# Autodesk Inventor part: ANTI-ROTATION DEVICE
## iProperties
Created: 2007-01
Part Number: ANTI-ROTATION DEVICE
Document SubType Name: Modeling
Designer: Andy Moles
Material: Aluminum-6061
Density: 2.71 g/cm^3
Mass: 6.76867 g
Surface Area: 23.7311 cm^2
Volume: 2.49766 cm^3
Author: Andy Moles
Title: ANTI ROTATION DEVICE
Keywords: ANTI-ROTATION DEVICE FOR ANGLES
Comments: ANTI ROTATION DEVICE FOR ANGLES BRACKETS AND MANY MINITEC PARTS
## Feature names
1. Extrusion1
2. Extrusion2
3. Extrusion3
